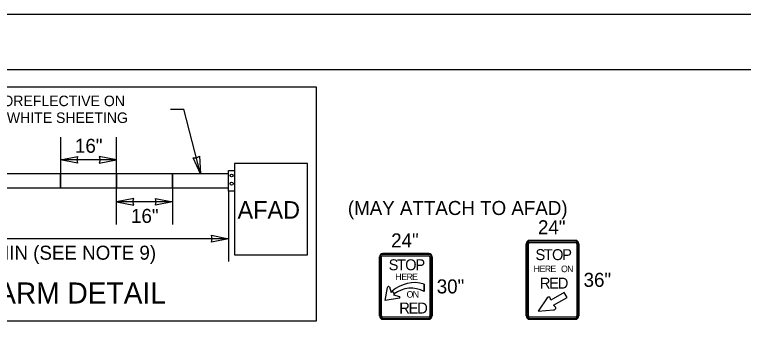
# Model space of a CAD drawing. Extents: x 99999.1 to 100095.7, y 99995 to 100010.7.
# Drawn here: x 100049.243 to 100053.402, y 100008.931 to 100010.687 of the extents above; entities that cross this region are included whole.
import ezdxf

# ---------------------------------------------------------------- set-up
doc = ezdxf.new("R2010")
doc.units = 0
for name, color, linetype in [('SH_GI_PlotLimits', 7, 'Continuous'), ('SH_GI_SheetBorder', 7, 'Continuous'), ('TR_SN_ConstructionSigns', 7, 'Continuous'), ('TR_WZ_WorkZoneDetails', 7, 'Continuous')]:
    doc.layers.add(name, color=color, linetype=linetype)

msp = doc.modelspace()

# ---------------------------------------------------------------- linework, layer by layer
at = {"layer": 'SH_GI_PlotLimits'}
msp.add_lwpolyline([(100039.0625, 99999.6875), (100056.0625, 99999.6875), (100056.0625, 100010.6875), (100039.0625, 100010.6875)], close=True, dxfattribs=at)
at = {"layer": 'SH_GI_SheetBorder'}
msp.add_line((100040, 100010.375), (100055.75, 100010.375), dxfattribs=at)
at = {"layer": 'TR_SN_ConstructionSigns'}
for p, q in [((100052.1629, 100009.3804), (100052.1629, 100008.9679)), ((100052.1629, 100008.9679), (100052.1629, 100009.3804)), ((100052.1629, 100009.3804), (100052.1629, 100008.9679)), ((100052.1676, 100009.3804), (100052.1676, 100008.9679)), ((100052.1754, 100008.9679), (100052.1754, 100009.3804)), ((100052.4441, 100009.3991), (100052.1816, 100009.3991)), ((100052.1816, 100009.3991), (100052.4441, 100009.3991)), ((100052.4441, 100009.3991), (100052.1816, 100009.3991)), ((100052.4441, 100009.3944), (100052.1816, 100009.3944)), ((100052.1816, 100009.3866), (100052.4441, 100009.3866)), ((100052.4504, 100009.3804), (100052.4504, 100008.9679)), ((100052.4582, 100008.9679), (100052.4582, 100009.3804)), ((100052.4629, 100008.9679), (100052.4629, 100009.3804)), ((100052.4629, 100009.3804), (100052.4629, 100008.9679)), ((100052.4629, 100008.9679), (100052.4629, 100009.3804)), ((100051.3249, 100009.3054), (100051.3249, 100008.9679)), ((100051.3249, 100008.9679), (100051.3249, 100009.3054)), ((100051.3249, 100009.3054), (100051.3249, 100008.9679)), ((100051.3249, 100008.9679), (100051.3249, 100009.3054)), ((100051.3296, 100009.3054), (100051.3296, 100008.9679)), ((100051.3374, 100008.9679), (100051.3374, 100009.3054)), ((100051.6061, 100009.3241), (100051.3436, 100009.3241)), ((100051.3436, 100009.3241), (100051.6061, 100009.3241)), ((100051.6061, 100009.3241), (100051.3436, 100009.3241)), ((100051.3436, 100009.3241), (100051.6061, 100009.3241)), ((100051.6061, 100009.3194), (100051.3436, 100009.3194)), ((100051.3436, 100009.3116), (100051.6061, 100009.3116)), ((100051.6124, 100009.3054), (100051.6124, 100008.9679)), ((100051.6202, 100008.9679), (100051.6202, 100009.3054)), ((100051.6249, 100008.9679), (100051.6249, 100009.3054)), ((100051.6249, 100009.3054), (100051.6249, 100008.9679)), ((100051.6249, 100008.9679), (100051.6249, 100009.3054)), ((100051.6249, 100009.3054), (100051.6249, 100008.9679)), ((100051.3577, 100009.0554), (100051.3713, 100009.1298)), ((100051.3821, 100009.1346), (100051.3915, 100009.1022)), ((100051.5798, 100009.1503), (100051.5795, 100009.1084)), ((100051.5795, 100009.1084), (100051.5798, 100009.1503)), ((100051.3915, 100009.1022), (100051.3979, 100009.1086)), ((100051.3979, 100009.1086), (100051.4095, 100009.0937)), ((100051.3979, 100009.1086), (100051.4095, 100009.0937)), ((100051.4095, 100009.0937), (100051.4048, 100009.0889)), ((100051.4048, 100009.0889), (100051.439, 100009.0797)), ((100052.3796, 100009.1022), (100052.303, 100009.058)), ((100052.396, 100009.0738), (100052.3796, 100009.1022)), ((100051.4388, 100009.0704), (100051.3577, 100009.0554)), ((100052.2824, 100009.0718), (100052.2298, 100008.9961)), ((100052.303, 100009.058), (100052.2992, 100009.0706)), ((100052.3186, 100009.0291), (100052.396, 100009.0738)), ((100052.2298, 100008.9961), (100052.3176, 100009.0022)), ((100052.3309, 100009.0154), (100052.3186, 100009.0291)), ((100051.6061, 100008.9616), (100051.3436, 100008.9616)), ((100052.4441, 100008.9616), (100052.1816, 100008.9616)), ((100051.3436, 100008.9538), (100051.6061, 100008.9538)), ((100051.3436, 100008.9491), (100051.6061, 100008.9491)), ((100051.6061, 100008.9491), (100051.3436, 100008.9491)), ((100051.3436, 100008.9491), (100051.6061, 100008.9491)), ((100051.6061, 100008.9491), (100051.3436, 100008.9491)), ((100052.1816, 100008.9538), (100052.4441, 100008.9538)), ((100052.1816, 100008.9491), (100052.4441, 100008.9491)), ((100052.4441, 100008.9491), (100052.1816, 100008.9491)), ((100052.1816, 100008.9491), (100052.4441, 100008.9491))]:
    msp.add_line(p, q, dxfattribs=at)
for centre, radius, start, end in [((100052.1816, 100009.3804), 0.0187, 90, 180), ((100052.1816, 100009.3804), 0.0187, 90, 180), ((100052.1816, 100009.3804), 0.0187, 90, 180), ((100052.1816, 100009.3804), 0.0141, 90, 180), ((100052.1816, 100009.3804), 0.00625, 90, 180), ((100052.4441, 100009.3804), 0.0187, 0, 90), ((100052.4441, 100009.3804), 0.0187, 0, 90), ((100052.4441, 100009.3804), 0.0187, 0, 90), ((100052.4441, 100009.3804), 0.0141, 0, 90), ((100052.4441, 100009.3804), 0.00625, 0, 90), ((100051.3436, 100009.3054), 0.0187, 90, 180), ((100051.3436, 100009.3054), 0.0187, 90, 180), ((100051.3436, 100009.3054), 0.0187, 90, 180), ((100051.3436, 100009.3054), 0.0187, 90, 180), ((100051.3436, 100009.3054), 0.0141, 90, 180), ((100051.3436, 100009.3054), 0.00625, 90, 180), ((100051.6061, 100009.3054), 0.0187, 0, 90), ((100051.6061, 100009.3054), 0.0187, 0, 90), ((100051.6061, 100009.3054), 0.0187, 0, 90), ((100051.6061, 100009.3054), 0.0187, 0, 90), ((100051.6061, 100009.3054), 0.0141, 0, 90), ((100051.6061, 100009.3054), 0.00625, 0, 90), ((100051.5261, 100008.9672), 0.1909, 73.6434, 132.2131), ((100051.5261, 100008.9672), 0.1909, 73.6434, 132.2131), ((100051.506, 100008.9678), 0.1586, 62.4149, 127.4769), ((100051.506, 100008.9678), 0.1586, 62.4149, 127.4769), ((100051.3436, 100008.9679), 0.0187, 180, 270), ((100051.3436, 100008.9679), 0.0187, 180, 270), ((100051.3436, 100008.9679), 0.0187, 180, 270), ((100051.3436, 100008.9679), 0.0187, 180, 270), ((100051.3436, 100008.9679), 0.0141, 180, 270), ((100051.3436, 100008.9679), 0.00625, 180, 270), ((100051.6061, 100008.9679), 0.0187, 270, 0), ((100051.6061, 100008.9679), 0.0187, 270, 0), ((100051.6061, 100008.9679), 0.0187, 270, 0), ((100051.6061, 100008.9679), 0.0141, 270, 0), ((100051.6061, 100008.9679), 0.00625, 270, 0), ((100051.6061, 100008.9679), 0.0187, 270, 0), ((100052.1816, 100008.9679), 0.0187, 180, 270), ((100052.1816, 100008.9679), 0.0187, 180, 270), ((100052.1816, 100008.9679), 0.0187, 180, 270), ((100052.1816, 100008.9679), 0.0141, 180, 270), ((100052.1816, 100008.9679), 0.00625, 180, 270), ((100052.4441, 100008.9679), 0.0187, 270, 0), ((100052.4441, 100008.9679), 0.0187, 270, 0), ((100052.4441, 100008.9679), 0.0187, 270, 0), ((100052.4441, 100008.9679), 0.0141, 270, 0), ((100052.4441, 100008.9679), 0.00625, 270, 0)]:
    msp.add_arc(centre, radius, start, end, dxfattribs=at)
for centre, major_axis, ratio, start_param, end_param in [((100051.3777, 100009.1299), (-0.00647, -0.00009), 0.989437, 3.962549, 6.283185), ((100051.4366, 100009.0751), (-0.0046, 0.00239), 0.999053, 2.490568, 4.712389), ((100052.2891, 100009.0675), (0.00934, 0.00539), 0.700347, 5.977036, 8.198856), ((100052.3216, 100009.0104), (-0.00913, -0.00527), 0.700347, 0.771965, 3.092601)]:
    msp.add_ellipse(centre, major_axis=major_axis, ratio=ratio, start_param=start_param, end_param=end_param, dxfattribs=at)
at = {"layer": 'TR_WZ_WorkZoneDetails'}
for p, q in [((100050.1326, 100010.147), (100050.2088, 100010.147)), ((100050.3043, 100009.779), (100050.2088, 100010.147)), ((100049.5043, 100009.989), (100049.5043, 100009.779)), ((100049.8243, 100009.779), (100049.8243, 100009.989)), ((100049.8243, 100009.859), (100049.5043, 100009.859)), ((100049.8243, 100009.489), (100049.8243, 100009.699)), ((100050.1443, 100009.699), (100050.1443, 100009.489)), ((100050.4643, 100009.6797), (100050.4643, 100009.279)), ((100050.1443, 100009.619), (100049.8243, 100009.619)), ((100050.4643, 100009.409), (100048.6643, 100009.409))]:
    msp.add_line(p, q, dxfattribs=at)
for points in [[(100047.6374, 100010.275), (100050.9639, 100010.275), (100050.9639, 100008.939), (100047.6374, 100008.939)], [(100049.5043, 100009.859), (100049.6026, 100009.8783), (100049.5981, 100009.859), (100049.6026, 100009.8397)], [(100049.8243, 100009.859), (100049.7261, 100009.8783), (100049.7306, 100009.859), (100049.7261, 100009.8397)], [(100050.3043, 100009.779), (100050.2611, 100009.8693), (100050.2809, 100009.8697), (100050.2984, 100009.879)], [(100050.4643, 100009.7983), (100050.4977, 100009.7983), (100050.4977, 100009.6797), (100050.4643, 100009.6797)], [(100049.8243, 100009.619), (100049.9226, 100009.5997), (100049.9181, 100009.619), (100049.9226, 100009.6383)], [(100050.1443, 100009.619), (100050.0461, 100009.5997), (100050.0506, 100009.619), (100050.0461, 100009.6383)], [(100050.4643, 100009.409), (100050.3661, 100009.3897), (100050.3706, 100009.409), (100050.3661, 100009.4283)]]:
    msp.add_lwpolyline(points, close=True, dxfattribs=at)
for points in [[(100050.4977, 100009.6797), (100050.4977, 100009.3163), (100050.9139, 100009.3163), (100050.9139, 100009.8374), (100050.4977, 100009.8374), (100050.4977, 100009.7983), (100050.4977, 100009.6797)], [(100050.9139, 100009.8374), (100050.4977, 100009.8374), (100050.4977, 100009.3163), (100050.9139, 100009.3163), (100050.9139, 100009.8374)], [(100050.4643, 100009.779), (100048.6643, 100009.779), (100048.6643, 100009.699), (100050.4643, 100009.699), (100050.4643, 100009.779)], [(100049.1843, 100009.699), (100049.5043, 100009.699), (100049.5043, 100009.779), (100049.1843, 100009.779), (100049.1843, 100009.699)], [(100049.5043, 100009.699), (100049.8243, 100009.699), (100049.8243, 100009.779), (100049.5043, 100009.779), (100049.5043, 100009.699)], [(100049.8243, 100009.699), (100050.1443, 100009.699), (100050.1443, 100009.779), (100049.8243, 100009.779), (100049.8243, 100009.699)], [(100050.1443, 100009.699), (100050.4643, 100009.699), (100050.4643, 100009.779), (100050.1443, 100009.779), (100050.1443, 100009.699)]]:
    msp.add_lwpolyline(points, dxfattribs=at)
for centre, radius in [((100050.4813, 100009.7693), 0.00828), ((100050.4813, 100009.7229), 0.00855)]:
    msp.add_circle(centre, radius, dxfattribs=at)

# ---------------------------------------------------------------- texts
at = {"layer": 'TR_SN_ConstructionSigns'}
for s, p in [('(MAY ATTACH TO AFAD)', (100051.1446, 100009.5441)), ('24"', (100052.2295, 100009.4341)), ('24"', (100051.3918, 100009.3591)), ('36"', (100052.4898, 100009.1341)), ('30"', (100051.6518, 100009.0966))]:
    msp.add_text(s, height=0.08, rotation=360, dxfattribs=at).set_placement(p)
for s, height, p in [('S', 0.0625, (100052.2154, 100009.2866)), ('T', 0.0625, (100052.2629, 100009.2866)), ('O', 0.0625, (100052.3097, 100009.2866)), ('P', 0.0625, (100052.3679, 100009.2866)), ('S', 0.0625, (100051.3774, 100009.2288)), ('O', 0.0625, (100051.4717, 100009.2288)), ('T', 0.0625, (100051.4249, 100009.2288)), ('P', 0.0625, (100051.5299, 100009.2288)), ('H', 0.0375, (100052.2043, 100009.2179)), ('E', 0.0375, (100052.2388, 100009.2179)), ('R', 0.0375, (100052.2684, 100009.2179)), ('E', 0.0375, (100052.3003, 100009.2179)), ('O', 0.0375, (100052.3611, 100009.2179)), ('N', 0.0375, (100052.3959, 100009.2179)), ('H', 0.0375, (100051.4152, 100009.1726)), ('E', 0.0375, (100051.4497, 100009.1726)), ('R', 0.0375, (100051.4794, 100009.1726)), ('E', 0.0375, (100051.5112, 100009.1726)), ('R', 0.0625, (100052.2404, 100009.1241)), ('E', 0.0625, (100052.2935, 100009.1241)), ('D', 0.0625, (100052.3429, 100009.1241)), ('O', 0.0375, (100051.4797, 100009.0726)), ('N', 0.0375, (100051.5146, 100009.0726)), ('R', 0.0625, (100051.4381, 100008.9819)), ('E', 0.0625, (100051.4913, 100008.9819)), ('D', 0.0625, (100051.5406, 100008.9819))]:
    msp.add_text(s, height=height, dxfattribs=at).set_placement(p)
at = {"layer": 'TR_WZ_WorkZoneDetails'}
for s, height, p in [('GATE ARM SHALL BE FULLY RETROREFLECTIVE ON', 0.06, (100047.8352, 100010.165)), ('BOTH SIDES WITH ALTERNATING RED/WHITE SHEETING', 0.06, (100047.6874, 100010.069)), ('16"', 0.08, (100049.5873, 100009.899)), ('AFAD', 0.1, (100050.5149, 100009.5231)), ('16"', 0.08, (100049.9073, 100009.499)), ('78" MIN (SEE NOTE 9)', 0.08, (100048.9363, 100009.289))]:
    msp.add_text(s, height=height, dxfattribs=at).set_placement(p)
msp.add_text('AFAD GATE ARM DETAIL', height=0.12, rotation=360, dxfattribs=at).set_placement((100048.1893, 100009.039))

doc.saveas('drawing.dxf')
